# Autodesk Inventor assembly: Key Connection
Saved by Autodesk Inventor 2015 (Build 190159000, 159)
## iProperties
Created: 2015-03
Part Number: Key Connection
Document SubType Name: Assembly
Designer: Uglješa
ClientObjectVersion: 1
Author: Uglješa
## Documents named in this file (2)
- C:\Users\Uglješa\Desktop\Turbokompr\Assembly1\Design Accelerator\Key Connection3.iam
- C:\Users\Uglješa\Documents\Inventor\Content Center Files\R2013\en-US\ISO 2491 - A\ISO 2491 - A  6 x 4 x 45.ipt
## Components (1 placed, 1 different names)
1. ISO 2491 A A  6 x 4 x 45:1
